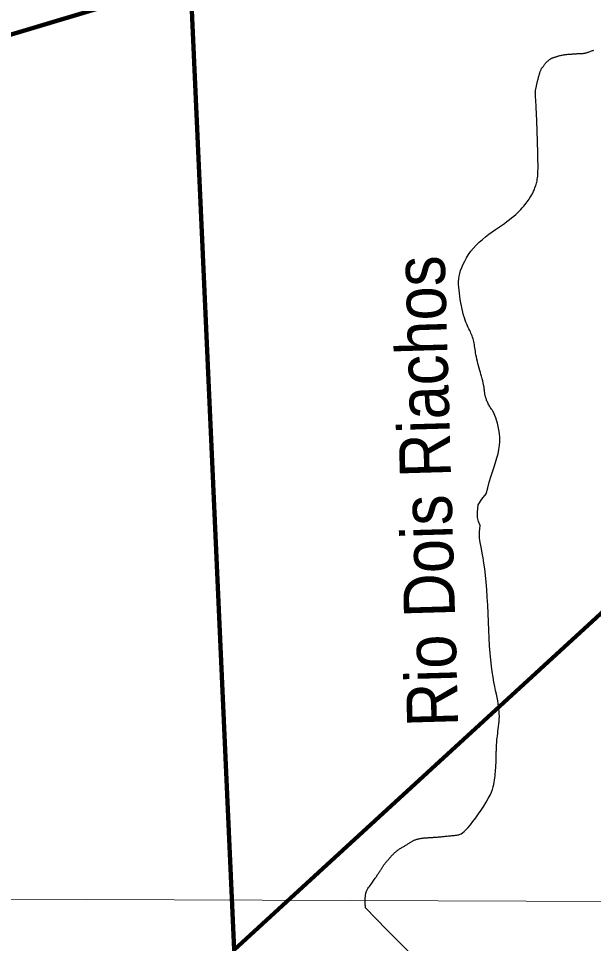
# Model space of a CAD drawing. Extents: x 553962 to 842807, y 8883888 to 9032388.
# Drawn here: x 703398 to 709028, y 8948937 to 8957994 of the extents above; entities that cross this region are included whole.
import ezdxf
from ezdxf.enums import TextEntityAlignment as Align

# ---------------------------------------------------------------- set-up
doc = ezdxf.new("R2010")
doc.units = 0
doc.header["$LTSCALE"] = 200
for name, color, linetype, lineweight in [('1', 7, 'Continuous', 13), ('24', 7, 'Continuous', 25), ('9', 7, 'Continuous', 90)]:
    doc.layers.add(name, color=color, linetype=linetype, lineweight=lineweight)
doc.layers.add('49', color=7, linetype='Continuous')

msp = doc.modelspace()

# ---------------------------------------------------------------- linework, layer by layer
at = {"layer": '1'}
msp.add_line((565315.3, 8949866.8), (791497.7, 8949052.2), dxfattribs=at)
at = {"layer": '24'}
for points in [[(708610.1, 8957600.3), (708613.9, 8957602.3), (708617.8, 8957604.2), (708621.9, 8957606), (708626.1, 8957607.8), (708630.4, 8957609.6), (708635, 8957611.3), (708639.8, 8957613.1), (708644.9, 8957614.8), (708650.2, 8957616.6), (708655.9, 8957618.4), (708661.8, 8957620.3), (708668.2, 8957622.2), (708674.8, 8957624.2), (708681.8, 8957626.2), (708689.2, 8957628.3), (708696.9, 8957630.4), (708704.8, 8957632.4), (708713, 8957634.4), (708721.5, 8957636.2), (708730.2, 8957637.9), (708739, 8957639.4), (708747.9, 8957640.7), (708757, 8957641.8), (708766, 8957642.8), (708774.9, 8957643.6), (708783.6, 8957644.3), (708792.1, 8957644.9), (708800.2, 8957645.4), (708807.8, 8957646), (708815, 8957646.5), (708821.7, 8957647), (708828, 8957647.5), (708834, 8957648), (708839.8, 8957648.5), (708845.3, 8957648.9), (708850.7, 8957649.2), (708856.1, 8957649.5), (708861.4, 8957649.7), (708866.8, 8957649.9), (708872.2, 8957650), (708877.6, 8957650.1), (708883.2, 8957650.2), (708888.8, 8957650.3), (708894.5, 8957650.5), (708900.4, 8957650.7), (708906.4, 8957651), (708912.5, 8957651.4), (708918.8, 8957651.9), (708925.2, 8957652.6), (708931.7, 8957653.4), (708938.3, 8957654.5), (708945, 8957655.8), (708951.8, 8957657.4), (708958.7, 8957659.2), (708965.6, 8957661.3), (708972.7, 8957663.7), (708979.8, 8957666.1), (708986.9, 8957668.7), (708994.2, 8957671.3), (709001.5, 8957674), (709008.9, 8957676.6), (709016.4, 8957679.2), (709023.9, 8957681.7), (709031.6, 8957684.3)], [(708437, 8956293.7), (708441.3, 8956303.2), (708445.5, 8956313.2), (708449.7, 8956323.7), (708453.8, 8956334.6), (708457.8, 8956345.8), (708461.7, 8956357.3), (708465.4, 8956369), (708468.9, 8956381), (708472.1, 8956393.1), (708475, 8956405.4), (708477.6, 8956418.6), (708479.8, 8956433.5), (708481.7, 8956451.1), (708483.1, 8956472), (708484.1, 8956497.2), (708484.6, 8956527.5), (708484.6, 8956563.7), (708484.1, 8956606.2), (708483.2, 8956654), (708481.8, 8956705.4), (708480.3, 8956759.1), (708478.5, 8956813.4), (708476.7, 8956866.9), (708474.8, 8956918), (708473.1, 8956965.2), (708471.5, 8957007.4), (708470, 8957044.6), (708468.7, 8957077.2), (708467.5, 8957105.9), (708466.3, 8957130.9), (708465.2, 8957152.8), (708464.2, 8957172), (708463.1, 8957189), (708462.1, 8957204.1), (708461.1, 8957217.7), (708460.1, 8957229.8), (708459.3, 8957240.7), (708458.7, 8957250.5), (708458.3, 8957259.4), (708458.2, 8957267.5), (708458.3, 8957275.2), (708458.9, 8957282.4), (708459.7, 8957289.3), (708460.8, 8957296), (708462.1, 8957302.5), (708463.6, 8957308.9), (708465.1, 8957315.2), (708466.7, 8957321.6), (708468.3, 8957328), (708469.8, 8957334.6), (708471.2, 8957341.3), (708472.7, 8957348.2), (708474.1, 8957355.1), (708475.6, 8957362.2), (708477.2, 8957369.4), (708478.8, 8957376.7), (708480.6, 8957384), (708482.5, 8957391.5), (708484.6, 8957398.9), (708486.7, 8957406.3), (708488.8, 8957413.7), (708490.9, 8957421), (708493, 8957428.1), (708495, 8957434.9), (708496.9, 8957441.6), (708498.7, 8957448), (708500.4, 8957454.1), (708502, 8957459.9), (708503.7, 8957465.6), (708505.4, 8957471.2), (708507.2, 8957476.6), (708509.3, 8957482), (708511.6, 8957487.3), (708514.1, 8957492.6), (708516.9, 8957497.9), (708520, 8957503.2), (708523.2, 8957508.4), (708526.6, 8957513.7), (708530.1, 8957518.8), (708533.6, 8957523.9), (708537.2, 8957529), (708540.8, 8957533.9), (708544.4, 8957538.8), (708548.1, 8957543.6), (708551.7, 8957548.3), (708555.4, 8957552.9), (708559.1, 8957557.3), (708562.9, 8957561.7), (708566.8, 8957565.8), (708570.7, 8957569.9), (708574.7, 8957573.8), (708578.7, 8957577.5), (708582.7, 8957581), (708586.8, 8957584.4), (708590.8, 8957587.5), (708594.7, 8957590.5), (708598.6, 8957593.2), (708602.5, 8957595.8), (708606.3, 8957598.1), (708610.1, 8957600.3)], [(707956, 8954384.1), (707954.9, 8954391.2), (707953.6, 8954398.5), (707952.2, 8954405.9), (707950.7, 8954413.4), (707949.1, 8954421), (707947.3, 8954428.8), (707945.3, 8954437.1), (707943, 8954446), (707940.4, 8954455.9), (707937.4, 8954466.9), (707933.9, 8954479.4), (707929.9, 8954493.6), (707925.3, 8954509.7), (707920.2, 8954528), (707914.5, 8954548.1), (707908.6, 8954569.4), (707902.5, 8954591.7), (707896.6, 8954614.5), (707890.9, 8954637.2), (707885.6, 8954659.4), (707881, 8954680.8), (707877.1, 8954701), (707873.8, 8954719.9), (707871.1, 8954737.8), (707868.7, 8954754.7), (707866.4, 8954770.9), (707864.2, 8954786.4), (707861.8, 8954801.5), (707859.2, 8954816.2), (707856.2, 8954830.6), (707852.6, 8954844.8), (707848.7, 8954858.9), (707844.3, 8954872.8), (707839.4, 8954886.5), (707834.1, 8954900.2), (707828.4, 8954913.7), (707822.2, 8954927.1), (707815.6, 8954940.5), (707808.6, 8954954.2), (707801.3, 8954968.6), (707793.8, 8954984.1), (707786.2, 8955000.9), (707778.5, 8955019.5), (707770.9, 8955040.3), (707763.3, 8955063.6), (707755.9, 8955089.6), (707748.8, 8955117.9), (707741.9, 8955148), (707735.5, 8955179.4), (707729.4, 8955211.4), (707724, 8955243.5), (707719, 8955275.2), (707714.8, 8955305.8), (707711.3, 8955335.1), (707708.8, 8955363.1), (707707.5, 8955390.3), (707707.6, 8955417.1), (707709.3, 8955443.8), (707713, 8955470.7), (707718.8, 8955498.4), (707727, 8955527), (707737.7, 8955556.9), (707751, 8955587.8), (707766.7, 8955619.4), (707784.9, 8955651.3), (707805.4, 8955683.3), (707828.1, 8955714.8), (707853.1, 8955745.7), (707880.1, 8955775.4), (707909.2, 8955803.8), (707939.8, 8955830.8), (707971.5, 8955856.6), (708003.7, 8955881.1), (708035.9, 8955904.5), (708067.7, 8955926.8), (708098.4, 8955948.1), (708127.7, 8955968.5), (708155, 8955988), (708180.5, 8956006.7), (708204.2, 8956024.7), (708226.2, 8956042.2), (708246.8, 8956059.2), (708265.9, 8956075.9), (708283.8, 8956092.2), (708300.4, 8956108.5), (708316.1, 8956124.6), (708330.7, 8956140.5), (708344.2, 8956156.1), (708356.8, 8956171.3), (708368.4, 8956185.9), (708378.9, 8956199.9), (708388.5, 8956213.1), (708397.1, 8956225.4), (708404.8, 8956236.7), (708411.5, 8956247.1), (708417.6, 8956257), (708423.1, 8956266.3), (708428, 8956275.5), (708432.6, 8956284.5), (708437, 8956293.7)], [(708079.3, 8954060.8), (708071.1, 8954085.7), (708063.2, 8954106.6), (708055.7, 8954124), (708048.6, 8954138.5), (708041.7, 8954150.6), (708035.2, 8954160.9), (708029.1, 8954169.9), (708023.1, 8954178.3), (708017.4, 8954186.5), (708012, 8954195), (708006.8, 8954203.9), (708001.8, 8954213), (707997.2, 8954222.1), (707992.8, 8954231.2), (707988.8, 8954240.2), (707985.1, 8954248.9), (707981.7, 8954257.1), (707978.7, 8954264.9), (707976, 8954272.2), (707973.6, 8954279.2), (707971.6, 8954285.9), (707969.7, 8954292.3), (707968.1, 8954298.6), (707966.8, 8954304.8), (707965.5, 8954311), (707964.5, 8954317.3), (707963.5, 8954323.6), (707962.7, 8954330.1), (707961.9, 8954336.5), (707961.2, 8954343.1), (707960.4, 8954349.7), (707959.7, 8954356.5), (707958.9, 8954363.2), (707958, 8954370.1), (707957.1, 8954377), (707956, 8954384.1)], [(708079.3, 8954060.8), (708071.1, 8954085.7), (708063.2, 8954106.6), (708055.7, 8954124), (708048.6, 8954138.5), (708041.7, 8954150.6), (708035.2, 8954160.9), (708029.1, 8954169.9), (708023.1, 8954178.3), (708017.4, 8954186.5), (708012, 8954195), (708006.8, 8954203.9), (708001.8, 8954213), (707997.2, 8954222.1), (707992.8, 8954231.2), (707988.8, 8954240.2), (707985.1, 8954248.9), (707981.7, 8954257.1), (707978.7, 8954264.9), (707976, 8954272.2), (707973.6, 8954279.2), (707971.6, 8954285.9), (707969.7, 8954292.3), (707968.1, 8954298.6), (707966.8, 8954304.8), (707965.5, 8954311), (707964.5, 8954317.3), (707963.5, 8954323.6), (707962.7, 8954330.1), (707961.9, 8954336.5), (707961.2, 8954343.1), (707960.4, 8954349.7), (707959.7, 8954356.5), (707958.9, 8954363.2), (707958, 8954370.1), (707957.1, 8954377), (707956, 8954384.1)], [(708105.3, 8951136), (708106, 8951160.4), (708105.7, 8951184.6), (708104.4, 8951208.7), (708102.1, 8951233.3), (708098.8, 8951258.8), (708094.7, 8951285.6), (708089.7, 8951314.1), (708083.8, 8951344.7), (708077, 8951378), (708069.6, 8951414.3), (708061.6, 8951454), (708053.2, 8951497.3), (708044.9, 8951544.7), (708036.7, 8951596.3), (708028.9, 8951652.5), (708021.8, 8951713.6), (708015.7, 8951780), (708010.6, 8951851.7), (708006.3, 8951927.7), (708002.7, 8952006.7), (707999.3, 8952087.6), (707996, 8952169.1), (707992.4, 8952249.9), (707988.2, 8952328.8), (707983.1, 8952404.7), (707977, 8952476.3), (707970, 8952543.3), (707962.4, 8952605.4), (707954.5, 8952662.4), (707946.5, 8952714.1), (707938.8, 8952760.1), (707931.6, 8952800.3), (707925.2, 8952834.3), (707919.7, 8952862.3), (707915.5, 8952885.6), (707912.4, 8952906.2), (707910.7, 8952925.7), (707910.4, 8952945.9), (707911.6, 8952968.7), (707914.4, 8952995.7), (707918.9, 8953028.8), (707901.9, 8953068.2), (707891.4, 8953109.1), (707891.4, 8953159.4), (707897.7, 8953232.7), (707934.3, 8953286.2), (707978.2, 8953339.4), (707992.2, 8953397.3), (708007.2, 8953453.2), (708022.7, 8953505.9), (708038.5, 8953555.7), (708053.9, 8953602.8), (708068.4, 8953647.8), (708081.6, 8953690.9), (708092.8, 8953732.6), (708101.7, 8953773.3), (708107.5, 8953813.5), (708110.1, 8953853.3), (708109.6, 8953892.4), (708106.6, 8953930.3), (708101.6, 8953966.7), (708095.1, 8954000.8), (708087.5, 8954032.4), (708079.3, 8954060.8)], [(708105.3, 8951136), (708106, 8951160.4), (708105.7, 8951184.6), (708104.4, 8951208.7), (708102.1, 8951233.3), (708098.8, 8951258.8), (708094.7, 8951285.6), (708089.7, 8951314.1), (708083.8, 8951344.7), (708077, 8951378), (708069.6, 8951414.3), (708061.6, 8951454), (708053.2, 8951497.3), (708044.9, 8951544.7), (708036.7, 8951596.3), (708028.9, 8951652.5), (708021.8, 8951713.6), (708015.7, 8951780), (708010.6, 8951851.7), (708006.3, 8951927.7), (708002.7, 8952006.7), (707999.3, 8952087.6), (707996, 8952169.1), (707992.4, 8952249.9), (707988.2, 8952328.8), (707983.1, 8952404.7), (707977, 8952476.3), (707970, 8952543.3), (707962.4, 8952605.4), (707954.5, 8952662.4), (707946.5, 8952714.1), (707938.8, 8952760.1), (707931.6, 8952800.3), (707925.2, 8952834.3), (707919.7, 8952862.3), (707915.5, 8952885.6), (707912.4, 8952906.2), (707910.7, 8952925.7), (707910.4, 8952945.9), (707911.6, 8952968.7), (707914.4, 8952995.7), (707918.9, 8953028.8), (707901.9, 8953068.2), (707891.4, 8953109.1), (707891.4, 8953159.4), (707897.7, 8953232.7), (707934.3, 8953286.2), (707978.2, 8953339.4), (707992.2, 8953397.3), (708007.2, 8953453.2), (708022.7, 8953505.9), (708038.5, 8953555.7), (708053.9, 8953602.8), (708068.4, 8953647.8), (708081.6, 8953690.9), (708092.8, 8953732.6), (708101.7, 8953773.3), (708107.5, 8953813.5), (708110.1, 8953853.3), (708109.6, 8953892.4), (708106.6, 8953930.3), (708101.6, 8953966.7), (708095.1, 8954000.8), (708087.5, 8954032.4), (708079.3, 8954060.8)], [(707335.3, 8949965.8), (707343.4, 8949967), (707351.5, 8949968.2), (707359.7, 8949969.2), (707368, 8949970.1), (707376.3, 8949971), (707384.6, 8949971.8), (707392.9, 8949972.5), (707401.3, 8949973.2), (707409.7, 8949973.8), (707418.2, 8949974.3), (707426.8, 8949974.9), (707435.5, 8949975.4), (707444.3, 8949975.9), (707453.3, 8949976.5), (707462.4, 8949977), (707471.6, 8949977.5), (707480.8, 8949978.1), (707490.1, 8949978.7), (707499.4, 8949979.3), (707508.7, 8949980.1), (707517.9, 8949980.8), (707527.1, 8949981.7), (707536.2, 8949982.6), (707545.5, 8949983.6), (707554.9, 8949984.6), (707564.5, 8949985.6), (707574.4, 8949986.7), (707584.7, 8949987.8), (707595.5, 8949988.9), (707606.7, 8949990), (707618.3, 8949991.1), (707630.1, 8949992.2), (707642.1, 8949993.3), (707654.1, 8949994.5), (707666, 8949995.7), (707677.6, 8949997), (707688.8, 8949998.3), (707699.6, 8949999.9), (707710.4, 8950002.2), (707721.5, 8950006), (707733.5, 8950012.1), (707746.8, 8950021), (707762, 8950033.6), (707779.3, 8950050.5), (707799.4, 8950072.5), (707822.3, 8950099.8), (707847.6, 8950131.9), (707874.3, 8950167.3), (707901.5, 8950205.1), (707928.3, 8950244.1), (707953.9, 8950283.2), (707977.4, 8950321.1), (707997.9, 8950356.8), (708014.7, 8950389.4), (708028.1, 8950419.1), (708038.5, 8950446.2), (708046.4, 8950471.1), (708052.2, 8950494.3), (708056.5, 8950516.3), (708059.6, 8950537.3), (708062.1, 8950557.8), (708064.2, 8950578.2), (708066.1, 8950598.2), (708067.8, 8950617.9), (708069.4, 8950636.8), (708070.7, 8950654.8), (708071.8, 8950671.8), (708072.8, 8950687.4), (708073.6, 8950701.6), (708074.2, 8950714.1), (708074.7, 8950725.1), (708075.1, 8950735), (708075.3, 8950743.8), (708075.5, 8950751.9), (708075.6, 8950759.5), (708075.7, 8950766.9), (708075.8, 8950774.2), (708075.9, 8950781.8), (708075.9, 8950789.6), (708076, 8950797.8), (708076.2, 8950806.4), (708076.3, 8950815.6), (708076.6, 8950825.3), (708076.8, 8950835.8), (708077.2, 8950846.9), (708077.7, 8950858.9), (708078.2, 8950871.8), (708079, 8950885.6), (708080, 8950900.5), (708081.2, 8950916.4), (708082.7, 8950933.6), (708084.7, 8950952), (708087, 8950971.7), (708089.7, 8950992.8), (708092.7, 8951015.1), (708095.8, 8951038.3), (708098.8, 8951062.2), (708101.5, 8951086.6), (708103.8, 8951111.3), (708105.3, 8951136)], [(707103, 8949843.3), (707109.6, 8949848.4), (707116.2, 8949853.3), (707122.7, 8949858), (707129.3, 8949862.5), (707136, 8949866.9), (707142.6, 8949871.1), (707149.3, 8949875.3), (707156.1, 8949879.4), (707162.9, 8949883.5), (707169.8, 8949887.6), (707176.7, 8949891.7), (707183.6, 8949895.8), (707190.4, 8949899.8), (707197.1, 8949903.8), (707203.7, 8949907.7), (707210, 8949911.6), (707216.1, 8949915.5), (707222, 8949919.2), (707227.5, 8949922.9), (707233, 8949926.5), (707238.3, 8949930), (707243.6, 8949933.4), (707248.9, 8949936.6), (707254.3, 8949939.8), (707259.8, 8949942.8), (707265.6, 8949945.6), (707271.6, 8949948.3), (707277.8, 8949950.8), (707284.2, 8949953.2), (707290.9, 8949955.5), (707297.8, 8949957.5), (707304.9, 8949959.5), (707312.2, 8949961.3), (707319.7, 8949962.9), (707327.4, 8949964.4), (707335.3, 8949965.8)], [(707005.5, 8949071.8), (706794.5, 8949287.1), (706791.8, 8949336), (706791.8, 8949375.1), (706794.1, 8949406), (706798.3, 8949430), (706803.9, 8949448.5), (706810.8, 8949462.9), (706818.3, 8949474.8), (706826.2, 8949485.3), (706834.1, 8949495.9), (706842, 8949506.5), (706849.7, 8949517.1), (706857.2, 8949527.6), (706864.4, 8949537.9), (706871.4, 8949547.9), (706878, 8949557.5), (706884.2, 8949566.6), (706890, 8949575.2), (706895.4, 8949583.2), (706900.5, 8949590.8), (706905.2, 8949598), (706909.8, 8949604.8), (706914.2, 8949611.4), (706918.5, 8949617.8), (706922.7, 8949624), (706926.9, 8949630.2), (706931, 8949636.2), (706935.2, 8949642.2), (706939.2, 8949648.1), (706943.1, 8949653.8), (706946.9, 8949659.5), (706950.5, 8949665), (706953.9, 8949670.4), (706957.1, 8949675.6), (706960.2, 8949680.7), (706963.2, 8949685.8), (706966.1, 8949690.8), (706969.2, 8949695.8), (706972.4, 8949700.9), (706975.8, 8949706), (706979.6, 8949711.2), (706983.6, 8949716.6), (706988, 8949722.1), (706992.7, 8949727.7), (706997.5, 8949733.4), (707002.5, 8949739.2), (707007.6, 8949745), (707012.8, 8949750.9), (707017.9, 8949756.7), (707023, 8949762.6), (707028, 8949768.5), (707033, 8949774.4), (707038.1, 8949780.3), (707043.2, 8949786.2), (707048.4, 8949792), (707053.8, 8949797.9), (707059.4, 8949803.8), (707065.2, 8949809.7), (707071.2, 8949815.5), (707077.3, 8949821.3), (707083.6, 8949827), (707090, 8949832.6), (707096.5, 8949838.1), (707103, 8949843.3)], [(707302.3, 8948774), (707005.5, 8949071.8)]]:
    msp.add_lwpolyline(points, dxfattribs=at)
at = {"layer": '9'}
for points in [[(691582, 8951218.7), (697371.2, 8956056), (705081.2, 8958366.8), (713138.6, 8969695)], [(705081.2, 8958366.8), (705509.2, 8948874.2), (720755.9, 8962863.6), (723053.6, 8963740.6)]]:
    msp.add_lwpolyline(points, dxfattribs=at)

# ---------------------------------------------------------------- texts
at = {"layer": '49', "width": 0.9}
msp.add_text('Rio Dois Riachos', height=500, rotation=91.671, dxfattribs=at).set_placement((707637.1, 8953371.6), align=Align.CENTER)

doc.saveas('drawing.dxf')
